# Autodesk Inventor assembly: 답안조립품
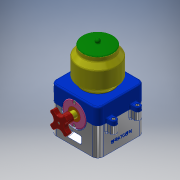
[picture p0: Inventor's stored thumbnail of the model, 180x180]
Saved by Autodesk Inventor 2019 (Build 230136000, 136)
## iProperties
Created: 2022-03
Part Number: 답안조립품
Material: 일반
Document SubType Name: Assembly
Designer: LINE501-2
Author: LINE501-2
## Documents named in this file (11)
- C:\Users\LINE501-2\Desktop\720306V1005\답안조립품.iam
- C:\Users\LINE501-2\Desktop\720306V1005\본체.ipt
- C:\Users\LINE501-2\Desktop\720306V1005\베어링 부시.ipt
- C:\Users\LINE501-2\Desktop\720306V1005\본체커버.ipt
- C:\Users\LINE501-2\Desktop\720306V1005\볼트 M3x12.ipt
- C:\Users\LINE501-2\Desktop\720306V1005\볼트 M4x12.ipt
- C:\Users\LINE501-2\Desktop\720306V1005\앞커버.ipt
- C:\Users\LINE501-2\Desktop\720306V1005\용기.ipt
- C:\Users\LINE501-2\Desktop\720306V1005\용기캡.ipt
- C:\Users\LINE501-2\Desktop\720306V1005\핸들.ipt
- C:\Users\LINE501-2\Desktop\720306V1005\핸들축.ipt
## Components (2 placed, 2 different names)
1. 핸들:1 — 각도:1
2. 핸들축:1 — 각도:1, 각도:2
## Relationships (2: Angle 2)
- 각도:1 [Angle]: 핸들:1 ↔ 핸들축:1
- 각도:2 [Angle]: 핸들축:1
